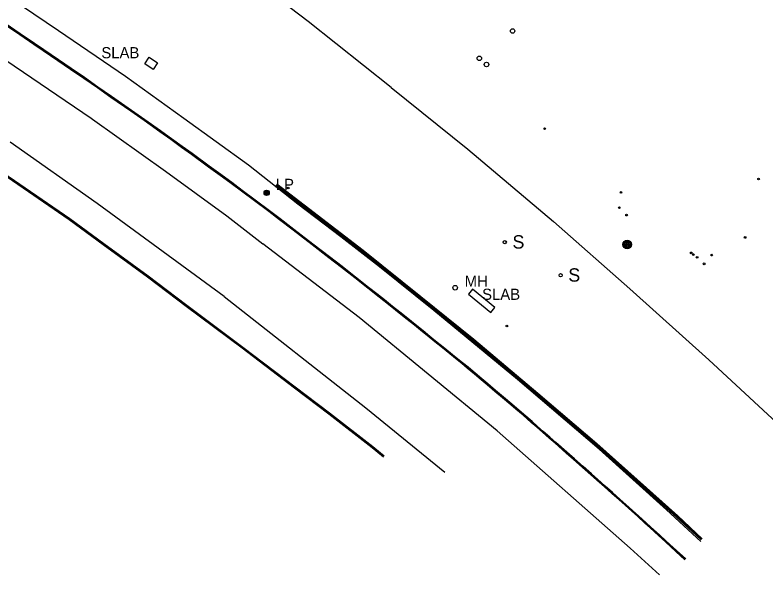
# Model space of a CAD drawing. Extents: x 368532 to 392481, y 10654822 to 10676899.
# Drawn here: x 372661.6 to 372999.3, y 10671324.6 to 10671576.3 of the extents above; entities that cross this region are included whole.
import ezdxf

# ---------------------------------------------------------------- set-up
doc = ezdxf.new("R2010")
doc.units = 0
for name, color, linetype in [('p_dtm sidewalk', 7, 'Continuous'), ('p_dtm slab', 7, 'Continuous'), ('p_railroad rr control', 7, 'Continuous'), ('p_road - paved curb', 7, 'Continuous'), ('p_road paint stripe', 7, 'Continuous'), ('p_structure sign', 7, 'Continuous'), ('p_structure unidentified', 7, 'Continuous'), ('p_structure wall', 7, 'Continuous'), ('p_utility general pole', 7, 'Continuous'), ('p_utility guy anchor', 7, 'Continuous'), ('p_utility manhole', 7, 'Continuous')]:
    doc.layers.add(name, color=color, linetype=linetype)

msp = doc.modelspace()

# ---------------------------------------------------------------- linework, layer by layer
at = {"layer": 'p_dtm sidewalk'}
for p, q in [((372681.17, 10671569.13), (372623.24, 10671608.48)), ((372711.31, 10671548.64), (372681.17, 10671569.13)), ((372737.49, 10671529.82), (372711.31, 10671548.64)), ((372766.64, 10671508.88), (372737.49, 10671529.82)), ((372788.76, 10671491.21), (372766.64, 10671508.88)), ((372808.16, 10671476.59), (372788.76, 10671491.21)), ((372825.47, 10671463.08), (372808.16, 10671476.59)), ((372849.94, 10671443.57), (372825.47, 10671463.08)), ((372887.49, 10671412.42), (372849.94, 10671443.57)), ((372924.28, 10671381.14), (372887.49, 10671412.42)), ((372954.52, 10671353.99), (372924.28, 10671381.14)), ((372970.02, 10671339.74), (372954.52, 10671353.99))]:
    msp.add_line(p, q, dxfattribs=at)
at = {"layer": 'p_dtm slab'}
for p, q in [((372719.94, 10671554.4), (372721.96, 10671557.4)), ((372721.96, 10671557.4), (372725.64, 10671554.73)), ((372723.68, 10671551.8), (372719.94, 10671554.4)), ((372725.64, 10671554.73), (372723.68, 10671551.8)), ((372867.39, 10671453.06), (372865.54, 10671450.83)), ((372877.38, 10671444.81), (372867.39, 10671453.06)), ((372865.54, 10671450.83), (372875.53, 10671442.58)), ((372875.53, 10671442.58), (372877.38, 10671444.81))]:
    msp.add_line(p, q, dxfattribs=at)
at = {"layer": 'p_railroad rr control'}
for points in [[(372830.77, 10671543.73), (372793.44, 10671573.35), (372743.01, 10671611.71), (372707.07, 10671637.94), (372671.62, 10671662.69), (372612.88, 10671702.83), (372559.17, 10671739.08), (372497.12, 10671781.26), (372449.85, 10671813.13), (372407.87, 10671841.39)], [(372830.77, 10671543.73), (372865.25, 10671516), (372903.7, 10671483.48), (372938.05, 10671453.26), (372973.59, 10671421.31), (373012.3, 10671385.52), (373028.43, 10671369.56)]]:
    msp.add_lwpolyline(points, dxfattribs=at)
at = {"layer": 'p_road - paved curb'}
for p, q in [((372663.71, 10671567.35), (372656.87, 10671572.06)), ((372663.79, 10671567.47), (372656.95, 10671572.18)), ((372663.99, 10671567.76), (372657.15, 10671572.47)), ((372670.07, 10671563.08), (372663.71, 10671567.35)), ((372670.15, 10671563.2), (372663.79, 10671567.47)), ((372670.35, 10671563.49), (372663.99, 10671567.76)), ((372674.6, 10671560.58), (372670.35, 10671563.49)), ((372674.32, 10671560.17), (372670.07, 10671563.08)), ((372674.4, 10671560.29), (372670.15, 10671563.2)), ((372680.85, 10671555.7), (372674.32, 10671560.17)), ((372680.93, 10671555.82), (372674.4, 10671560.29)), ((372681.13, 10671556.11), (372674.6, 10671560.58)), ((372686.53, 10671551.85), (372680.85, 10671555.7)), ((372686.61, 10671551.97), (372680.93, 10671555.82)), ((372686.81, 10671552.26), (372681.13, 10671556.11)), ((372692.51, 10671547.74), (372686.53, 10671551.85)), ((372692.6, 10671547.86), (372686.61, 10671551.97)), ((372692.79, 10671548.15), (372686.81, 10671552.26)), ((372698.63, 10671543.5), (372692.51, 10671547.74)), ((372698.72, 10671543.62), (372692.6, 10671547.86)), ((372698.92, 10671543.91), (372692.79, 10671548.15)), ((372704.72, 10671539.24), (372698.63, 10671543.5)), ((372704.81, 10671539.36), (372698.72, 10671543.62)), ((372705.01, 10671539.65), (372698.92, 10671543.91)), ((372713.7, 10671533.02), (372704.72, 10671539.24)), ((372713.79, 10671533.14), (372704.81, 10671539.36)), ((372713.99, 10671533.43), (372705.01, 10671539.65)), ((372719.65, 10671528.84), (372713.7, 10671533.02)), ((372719.74, 10671528.96), (372713.79, 10671533.14)), ((372719.94, 10671529.25), (372713.99, 10671533.43)), ((372726.68, 10671523.82), (372719.65, 10671528.84)), ((372726.77, 10671523.94), (372719.74, 10671528.96)), ((372726.97, 10671524.23), (372719.94, 10671529.25)), ((372731.67, 10671520.29), (372726.68, 10671523.82)), ((372731.76, 10671520.41), (372726.77, 10671523.94)), ((372731.96, 10671520.7), (372726.97, 10671524.23)), ((372632.56, 10671520.96), (372685.91, 10671484.4)), ((372632.75, 10671521.25), (372686.11, 10671484.69)), ((372632.84, 10671521.37), (372686.2, 10671484.81)), ((372736.53, 10671516.8), (372731.67, 10671520.29)), ((372736.62, 10671516.92), (372731.76, 10671520.41)), ((372736.82, 10671517.21), (372731.96, 10671520.7)), ((372740.98, 10671513.59), (372736.53, 10671516.8)), ((372741.07, 10671513.71), (372736.62, 10671516.92)), ((372741.27, 10671513.99), (372736.82, 10671517.21)), ((372748.59, 10671507.97), (372740.98, 10671513.59)), ((372748.68, 10671508.09), (372741.07, 10671513.71)), ((372748.88, 10671508.37), (372741.27, 10671513.99)), ((372753.8, 10671504.21), (372748.59, 10671507.97)), ((372753.89, 10671504.33), (372748.68, 10671508.09)), ((372754.09, 10671504.61), (372748.88, 10671508.37)), ((372758.74, 10671500.57), (372753.8, 10671504.21)), ((372758.83, 10671500.69), (372753.89, 10671504.33)), ((372759.04, 10671500.97), (372754.09, 10671504.61)), ((372763.43, 10671497.09), (372758.74, 10671500.57)), ((372763.52, 10671497.21), (372758.83, 10671500.69)), ((372763.73, 10671497.49), (372759.04, 10671500.97)), ((372769.34, 10671492.73), (372763.43, 10671497.09)), ((372769.43, 10671492.85), (372763.52, 10671497.21)), ((372769.64, 10671493.13), (372763.73, 10671497.49)), ((372775.81, 10671487.93), (372769.34, 10671492.73)), ((372775.9, 10671488.05), (372769.43, 10671492.85)), ((372776.11, 10671488.33), (372769.64, 10671493.13)), ((372780.51, 10671484.3), (372775.81, 10671487.93)), ((372780.6, 10671484.42), (372775.9, 10671488.05)), ((372780.82, 10671484.7), (372776.11, 10671488.33)), ((372685.91, 10671484.4), (372701.19, 10671473.23)), ((372686.11, 10671484.69), (372701.4, 10671473.51)), ((372686.2, 10671484.81), (372701.49, 10671473.63)), ((372786.64, 10671479.57), (372780.51, 10671484.3)), ((372786.73, 10671479.69), (372780.6, 10671484.42)), ((372786.94, 10671479.97), (372780.82, 10671484.7)), ((372790, 10671476.99), (372786.64, 10671479.57)), ((372790.09, 10671477.11), (372786.73, 10671479.69)), ((372790.31, 10671477.39), (372786.94, 10671479.97)), ((372795.19, 10671472.96), (372790, 10671476.99)), ((372795.28, 10671473.08), (372790.09, 10671477.11)), ((372795.5, 10671473.36), (372790.31, 10671477.39)), ((372701.19, 10671473.23), (372721.2, 10671458.65)), ((372701.4, 10671473.51), (372721.41, 10671458.93)), ((372701.49, 10671473.63), (372721.49, 10671459.05)), ((372802.75, 10671467.16), (372795.19, 10671472.96)), ((372802.84, 10671467.28), (372795.28, 10671473.08)), ((372803.05, 10671467.56), (372795.5, 10671473.36)), ((372808.41, 10671462.81), (372802.75, 10671467.16)), ((372808.5, 10671462.93), (372802.84, 10671467.28)), ((372808.72, 10671463.21), (372803.05, 10671467.56)), ((372814.41, 10671458.14), (372808.41, 10671462.81)), ((372814.5, 10671458.26), (372808.5, 10671462.93)), ((372814.72, 10671458.53), (372808.72, 10671463.21)), ((372721.41, 10671458.93), (372738.82, 10671445.77)), ((372721.49, 10671459.05), (372738.91, 10671445.89)), ((372721.2, 10671458.65), (372738.61, 10671445.49)), ((372820.29, 10671453.49), (372814.41, 10671458.14)), ((372820.38, 10671453.61), (372814.5, 10671458.26)), ((372820.6, 10671453.88), (372814.72, 10671458.53)), ((372823.97, 10671450.56), (372820.29, 10671453.49)), ((372824.06, 10671450.68), (372820.38, 10671453.61)), ((372824.28, 10671450.95), (372820.6, 10671453.88)), ((372827.38, 10671447.87), (372823.97, 10671450.56)), ((372827.47, 10671447.99), (372824.06, 10671450.68)), ((372827.69, 10671448.26), (372824.28, 10671450.95)), ((372738.61, 10671445.49), (372763.76, 10671426.68)), ((372738.82, 10671445.77), (372763.97, 10671426.96)), ((372738.91, 10671445.89), (372764.06, 10671427.08)), ((372831.1, 10671444.93), (372827.38, 10671447.87)), ((372831.19, 10671445.05), (372827.47, 10671447.99)), ((372831.41, 10671445.32), (372827.69, 10671448.26)), ((372834.62, 10671442.76), (372831.41, 10671445.32)), ((372834.31, 10671442.37), (372831.1, 10671444.93)), ((372834.4, 10671442.49), (372831.19, 10671445.05)), ((372837.92, 10671439.52), (372834.31, 10671442.37)), ((372838.01, 10671439.64), (372834.4, 10671442.49)), ((372838.23, 10671439.91), (372834.62, 10671442.76)), ((372841.2, 10671436.89), (372837.92, 10671439.52)), ((372841.29, 10671437.01), (372838.01, 10671439.64)), ((372841.51, 10671437.28), (372838.23, 10671439.91)), ((372844.84, 10671433.92), (372841.2, 10671436.89)), ((372844.93, 10671434.04), (372841.29, 10671437.01)), ((372845.16, 10671434.31), (372841.51, 10671437.28)), ((372847.85, 10671431.49), (372844.84, 10671433.92)), ((372847.94, 10671431.61), (372844.93, 10671434.04)), ((372848.16, 10671431.88), (372845.16, 10671434.31)), ((372850.75, 10671429.79), (372848.16, 10671431.88)), ((372850.44, 10671429.4), (372847.85, 10671431.49)), ((372850.53, 10671429.52), (372847.94, 10671431.61)), ((372853.8, 10671426.67), (372850.44, 10671429.4)), ((372853.89, 10671426.79), (372850.53, 10671429.52)), ((372854.12, 10671427.06), (372850.75, 10671429.79)), ((372763.76, 10671426.68), (372787.25, 10671408.77)), ((372763.97, 10671426.96), (372787.47, 10671409.05)), ((372764.06, 10671427.08), (372787.56, 10671409.17)), ((372857.06, 10671424), (372853.8, 10671426.67)), ((372857.15, 10671424.12), (372853.89, 10671426.79)), ((372857.38, 10671424.39), (372854.12, 10671427.06)), ((372859.67, 10671421.89), (372857.06, 10671424)), ((372859.76, 10671422.01), (372857.15, 10671424.12)), ((372859.99, 10671422.28), (372857.38, 10671424.39)), ((372862.45, 10671419.61), (372859.67, 10671421.89)), ((372862.54, 10671419.73), (372859.76, 10671422.01)), ((372862.77, 10671420), (372859.99, 10671422.28)), ((372864.99, 10671417.57), (372862.45, 10671419.61)), ((372865.09, 10671417.69), (372862.54, 10671419.73)), ((372865.31, 10671417.96), (372862.77, 10671420)), ((372868.19, 10671414.89), (372864.99, 10671417.57)), ((372868.29, 10671415), (372865.09, 10671417.69)), ((372868.51, 10671415.27), (372865.31, 10671417.96)), ((372871.18, 10671412.37), (372868.19, 10671414.89)), ((372871.28, 10671412.48), (372868.29, 10671415)), ((372871.5, 10671412.75), (372868.51, 10671415.27)), ((372873.85, 10671410.12), (372871.18, 10671412.37)), ((372873.95, 10671410.23), (372871.28, 10671412.48)), ((372874.17, 10671410.5), (372871.5, 10671412.75)), ((372787.25, 10671408.77), (372802.65, 10671397.04)), ((372787.47, 10671409.05), (372802.86, 10671397.32)), ((372787.56, 10671409.17), (372802.95, 10671397.44)), ((372877.38, 10671407.14), (372873.85, 10671410.12)), ((372877.48, 10671407.25), (372873.95, 10671410.23)), ((372877.7, 10671407.52), (372874.17, 10671410.5)), ((372880.87, 10671404.21), (372877.38, 10671407.14)), ((372880.97, 10671404.32), (372877.48, 10671407.25)), ((372881.19, 10671404.59), (372877.7, 10671407.52)), ((372884.61, 10671401.05), (372880.87, 10671404.21)), ((372884.71, 10671401.16), (372880.97, 10671404.32)), ((372884.93, 10671401.43), (372881.19, 10671404.59)), ((372887.15, 10671399.56), (372884.93, 10671401.43)), ((372886.83, 10671399.18), (372884.61, 10671401.05)), ((372886.93, 10671399.29), (372884.71, 10671401.16)), ((372890.06, 10671396.45), (372886.83, 10671399.18)), ((372890.16, 10671396.56), (372886.93, 10671399.29)), ((372890.39, 10671396.83), (372887.15, 10671399.56)), ((372802.65, 10671397.04), (372822.24, 10671381.95)), ((372802.86, 10671397.32), (372822.45, 10671382.22)), ((372802.95, 10671397.44), (372822.55, 10671382.34)), ((372893.76, 10671393.21), (372890.06, 10671396.45)), ((372893.86, 10671393.32), (372890.16, 10671396.56)), ((372894.09, 10671393.59), (372890.39, 10671396.83)), ((372896.23, 10671391.04), (372893.76, 10671393.21)), ((372896.33, 10671391.15), (372893.86, 10671393.32)), ((372896.56, 10671391.42), (372894.09, 10671393.59)), ((372899.14, 10671389.17), (372896.56, 10671391.42)), ((372898.81, 10671388.79), (372896.23, 10671391.04)), ((372898.91, 10671388.9), (372896.33, 10671391.15)), ((372901.78, 10671386.19), (372898.81, 10671388.79)), ((372901.88, 10671386.3), (372898.91, 10671388.9)), ((372902.11, 10671386.57), (372899.14, 10671389.17)), ((372904.49, 10671383.81), (372901.78, 10671386.19)), ((372904.59, 10671383.92), (372901.88, 10671386.3)), ((372904.82, 10671384.19), (372902.11, 10671386.57)), ((372822.24, 10671381.95), (372827.23, 10671377.77)), ((372822.45, 10671382.22), (372827.45, 10671378.04)), ((372822.55, 10671382.34), (372827.55, 10671378.15)), ((372909.46, 10671379.44), (372904.49, 10671383.81)), ((372909.56, 10671379.55), (372904.59, 10671383.92)), ((372909.79, 10671379.82), (372904.82, 10671384.19)), ((372912.79, 10671376.5), (372909.46, 10671379.44)), ((372912.89, 10671376.61), (372909.56, 10671379.55)), ((372913.12, 10671376.87), (372909.79, 10671379.82)), ((372916.75, 10671372.98), (372912.79, 10671376.5)), ((372916.85, 10671373.09), (372912.89, 10671376.61)), ((372917.08, 10671373.35), (372913.12, 10671376.87)), ((372920.46, 10671369.72), (372916.75, 10671372.98)), ((372920.56, 10671369.83), (372916.85, 10671373.09)), ((372920.79, 10671370.09), (372917.08, 10671373.35)), ((372923.17, 10671367.29), (372920.46, 10671369.72)), ((372923.27, 10671367.4), (372920.56, 10671369.83)), ((372923.5, 10671367.66), (372920.79, 10671370.09)), ((372926.97, 10671364.6), (372923.5, 10671367.66)), ((372926.64, 10671364.23), (372923.17, 10671367.29)), ((372926.74, 10671364.34), (372923.27, 10671367.4)), ((372929.93, 10671361.3), (372926.64, 10671364.23)), ((372930.03, 10671361.41), (372926.74, 10671364.34)), ((372930.26, 10671361.67), (372926.97, 10671364.6)), ((372933.22, 10671358.37), (372929.93, 10671361.3)), ((372933.32, 10671358.48), (372930.03, 10671361.41)), ((372933.55, 10671358.74), (372930.26, 10671361.67)), ((372935.96, 10671355.95), (372933.22, 10671358.37)), ((372936.06, 10671356.06), (372933.32, 10671358.48)), ((372936.29, 10671356.32), (372933.55, 10671358.74)), ((372939, 10671353.25), (372935.96, 10671355.95)), ((372939.1, 10671353.36), (372936.06, 10671356.06)), ((372939.33, 10671353.62), (372936.29, 10671356.32)), ((372941.67, 10671350.88), (372939, 10671353.25)), ((372941.77, 10671350.99), (372939.1, 10671353.36)), ((372942.01, 10671351.25), (372939.33, 10671353.62)), ((372944.86, 10671347.92), (372941.67, 10671350.88)), ((372944.96, 10671348.03), (372941.77, 10671350.99)), ((372945.2, 10671348.29), (372942.01, 10671351.25)), ((372947.16, 10671345.83), (372944.86, 10671347.92)), ((372947.26, 10671345.94), (372944.96, 10671348.03)), ((372947.5, 10671346.2), (372945.2, 10671348.29)), ((372950.99, 10671342.32), (372947.16, 10671345.83)), ((372951.09, 10671342.43), (372947.26, 10671345.94)), ((372951.33, 10671342.69), (372947.5, 10671346.2)), ((372954.12, 10671339.47), (372950.99, 10671342.32)), ((372954.22, 10671339.58), (372951.09, 10671342.43)), ((372954.46, 10671339.84), (372951.33, 10671342.69)), ((372958.71, 10671335.27), (372954.12, 10671339.47)), ((372958.81, 10671335.38), (372954.22, 10671339.58)), ((372959.05, 10671335.64), (372954.46, 10671339.84)), ((372962.85, 10671331.46), (372958.71, 10671335.27)), ((372962.95, 10671331.57), (372958.81, 10671335.38)), ((372963.19, 10671331.83), (372959.05, 10671335.64))]:
    msp.add_line(p, q, dxfattribs=at)
at = {"layer": 'p_road paint stripe'}
for p, q in [((372597.17, 10671596.65), (372695.92, 10671529.94)), ((372695.92, 10671529.94), (372696.49, 10671529.52)), ((372696.49, 10671529.52), (372729.31, 10671506.16)), ((372698.56, 10671491.61), (372659.45, 10671519.2)), ((372729.31, 10671506.16), (372756.88, 10671486.01)), ((372755.65, 10671449.78), (372698.56, 10671491.61)), ((372756.88, 10671486.01), (372773.09, 10671473.44)), ((372816.34, 10671440.3), (372773.09, 10671473.44)), ((372755.65, 10671449.78), (372819.31, 10671399.73)), ((372878.45, 10671389.41), (372816.34, 10671440.3)), ((372819.31, 10671399.73), (372854.82, 10671370.8)), ((372938.23, 10671336.73), (372878.45, 10671389.41)), ((372951.39, 10671324.65), (372938.23, 10671336.73))]:
    msp.add_line(p, q, dxfattribs=at)
at = {"layer": 'p_structure sign'}
for centre in [(372881.83, 10671474.22), (372906.93, 10671459.35)]:
    msp.add_circle(centre, 0.713, dxfattribs=at)
at = {"layer": 'p_structure unidentified'}
for centre in [(372899.73, 10671525.19), (372995.94, 10671502.57), (372784.47, 10671498.52), (372934.1, 10671496.53), (372933.36, 10671489.7), (372936.57, 10671486.38), (372989.91, 10671476.33), (372965.66, 10671469.41), (372966.6, 10671468.63), (372968.31, 10671467.4), (372974.88, 10671468.4), (372971.45, 10671464.47), (372882.79, 10671436.52)]:
    msp.add_circle(centre, 0.375, dxfattribs=at)
at = {"layer": 'p_structure wall'}
for p, q in [((372778.92, 10671499.82), (372817.65, 10671470.05)), ((372779.15, 10671500.12), (372817.88, 10671470.35)), ((372779.39, 10671500.42), (372818.12, 10671470.65)), ((372817.65, 10671470.05), (372843.65, 10671449.24)), ((372817.88, 10671470.35), (372843.89, 10671449.53)), ((372818.12, 10671470.65), (372844.13, 10671449.83)), ((372843.65, 10671449.24), (372867.48, 10671430.08)), ((372843.89, 10671449.53), (372867.73, 10671430.38)), ((372844.13, 10671449.83), (372867.97, 10671430.67)), ((372867.48, 10671430.08), (372896.26, 10671405.82)), ((372867.73, 10671430.38), (372896.51, 10671406.11)), ((372867.97, 10671430.67), (372896.75, 10671406.4)), ((372896.26, 10671405.82), (372922.78, 10671383.17)), ((372896.51, 10671406.11), (372923.03, 10671383.46)), ((372896.75, 10671406.4), (372923.28, 10671383.75)), ((372922.78, 10671383.17), (372944.99, 10671363.17)), ((372923.03, 10671383.46), (372945.25, 10671363.45)), ((372923.28, 10671383.75), (372945.5, 10671363.74)), ((372944.99, 10671363.17), (372959.07, 10671350.61)), ((372945.25, 10671363.45), (372959.32, 10671350.9)), ((372945.5, 10671363.74), (372959.58, 10671351.18)), ((372959.32, 10671350.9), (372970.29, 10671340.77)), ((372959.58, 10671351.18), (372970.64, 10671340.96)), ((372959.07, 10671350.61), (372970.17, 10671340.37))]:
    msp.add_line(p, q, dxfattribs=at)
at = {"layer": 'p_utility general pole'}
for centre, radius in [((372774.76, 10671496.38), 1.19), ((372774.76, 10671496.38), 0.901), ((372774.76, 10671496.38), 0.608), ((372774.76, 10671496.38), 0.337), ((372774.76, 10671496.38), 0.12), ((372936.86, 10671473.14), 1.9), ((372936.86, 10671473.14), 1.44), ((372936.86, 10671473.14), 0.973), ((372936.86, 10671473.14), 0.539), ((372936.86, 10671473.14), 0.192)]:
    msp.add_circle(centre, radius, dxfattribs=at)
at = {"layer": 'p_utility guy anchor'}
for centre in [(372885.34, 10671569.12), (372870.39, 10671556.84), (372873.6, 10671554.05)]:
    msp.add_circle(centre, 1, dxfattribs=at)
at = {"layer": 'p_utility manhole'}
msp.add_circle((372859.52, 10671453.72), 1.05, dxfattribs=at)

# ---------------------------------------------------------------- texts
at = {"layer": 'p_dtm slab'}
for p in [(372698.57, 10671556.85), (372869.77, 10671448.29)]:
    msp.add_text(' SLAB', height=5, dxfattribs=at).set_placement(p)
at = {"layer": 'p_structure sign'}
for p in [(372885.29, 10671471.33), (372910.39, 10671456.46)]:
    msp.add_text('S', height=6, dxfattribs=at).set_placement(p)
at = {"layer": 'p_utility general pole'}
msp.add_text('LP', height=5, dxfattribs=at).set_placement((372778.88, 10671497.67))
at = {"layer": 'p_utility manhole'}
msp.add_text('MH', height=5, dxfattribs=at).set_placement((372863.79, 10671454.19))

doc.saveas('drawing.dxf')
